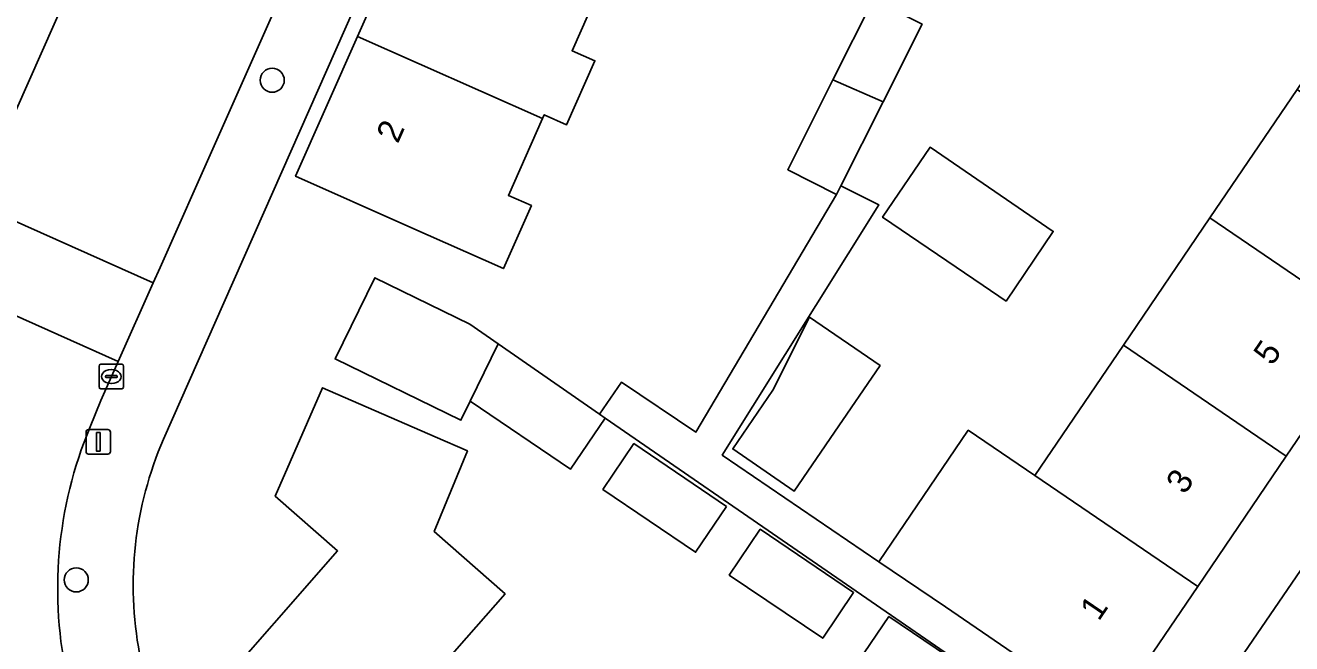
# Model space of a CAD drawing. Extents: x 160023 to 161302, y 384750 to 385707.
# Drawn here: x 160150 to 160201.5, y 385275.6 to 385300.7 of the extents above; entities that cross this region are included whole.
import ezdxf

# ---------------------------------------------------------------- set-up
doc = ezdxf.new("R2010")
doc.units = 0
for name, color, linetype in [('IMGEO_Boom', 7, 'Continuous'), ('IMGEO_Erf', 7, 'Continuous'), ('IMGEO_Kolk', 7, 'Continuous'), ('IMGEO_Lichtmast', 7, 'Continuous'), ('IMGEO_Pand', 7, 'Continuous'), ('IMGEO_Pand_nummerreeks', 7, 'Continuous'), ('IMGEO_Rijbaan_lokaal_gesloten', 7, 'Continuous'), ('IMGEO_Rijbaan_lokaal_open', 7, 'Continuous'), ('IMGEO_Voetpad_open', 7, 'Continuous')]:
    doc.layers.add(name, color=color, linetype=linetype)

msp = doc.modelspace()

# ---------------------------------------------------------------- linework, layer by layer
at = {"layer": 'IMGEO_Boom'}
for centre in [(160160.018, 385298.496), (160152.044, 385278.181)]:
    msp.add_circle(centre, 0.489, dxfattribs=at)
at = {"layer": 'IMGEO_Erf'}
for points in [[(160183.431, 385346.744), (160159.311, 385292.29), (160158.414, 385290.267), (160155.597, 385283.906)], [(160173.529, 385302.648), (160172.22, 385299.697), (160173.147, 385299.286), (160171.995, 385296.689), (160171.085, 385297.093), (160171.015, 385296.934), (160169.631, 385293.814), (160170.564, 385293.401), (160169.426, 385290.836), (160165.536, 385292.563), (160160.965, 385294.59), (160163.487, 385300.274), (160166.018, 385305.98)], [(160186.466, 385300.778), (160184.874, 385297.615), (160183.158, 385294.204), (160184.707, 385293.425), (160178.329, 385283.256), (160184.707, 385278.922), (160188.342, 385284.267), (160191.051, 385282.425), (160194.656, 385287.725), (160198.174, 385292.898), (160201.722, 385298.115), (160205.269, 385303.332)], [(160190.417, 385273.159), (160173.571, 385284.757), (160172.15, 385282.683), (160168.075, 385285.45), (160167.694, 385284.67), (160162.577, 385287.169), (160164.187, 385290.467), (160168.065, 385288.573), (160169.21, 385287.779), (160173.331, 385284.924), (160174.229, 385286.22), (160177.261, 385284.188), (160182.983, 385293.857), (160180.994, 385294.858), (160182.836, 385298.519), (160184.476, 385301.779)], [(160157.419, 385273.368), (160162.676, 385279.36), (160160.143, 385281.583), (160162.064, 385285.991), (160166.648, 385283.994), (160167.959, 385283.423), (160166.609, 385280.144), (160169.496, 385277.611), (160167.531, 385275.372)]]:
    msp.add_lwpolyline(points, dxfattribs=at)
for points in [[(160221.619, 385307.412), (160218.975, 385309.223), (160215.422, 385303.999), (160211.901, 385298.822), (160208.353, 385293.604), (160204.806, 385288.388), (160201.287, 385283.214), (160197.683, 385277.915), (160194.049, 385272.571), (160196.571, 385270.843)], [(160186.787, 385295.774), (160191.803, 385292.348), (160189.88, 385289.515), (160188.943, 385290.151), (160184.854, 385292.928)], [(160180.395, 385285.892), (160181.882, 385288.862), (160184.754, 385286.898), (160182.895, 385284.181), (160181.262, 385281.794), (160178.762, 385283.505)], [(160178.509, 385281.166), (160177.249, 385279.307), (160173.478, 385281.86), (160174.737, 385283.72)], [(160183.679, 385277.665), (160182.419, 385275.806), (160178.617, 385278.38), (160179.877, 385280.239)], [(160188.923, 385274.114), (160187.664, 385272.254), (160183.852, 385274.836), (160185.112, 385276.695)]]:
    msp.add_lwpolyline(points, close=True, dxfattribs=at)
msp.add_arc((160169.229, 385277.966), 14.87, 156.4566, 190.8082, dxfattribs=at)
at = {"layer": 'IMGEO_Kolk'}
for p, q in [((160152.97, 385286.024), (160152.97, 385286.876)), ((160153.045, 385286.95), (160153.897, 385286.95)), ((160153.458, 385286.73), (160153.483, 385286.73)), ((160153.971, 385286.876), (160153.971, 385286.024)), ((160153.229, 385286.444), (160153.229, 385286.456)), ((160153.667, 385286.407), (160153.269, 385286.407)), ((160153.272, 385286.493), (160153.67, 385286.493)), ((160153.481, 385286.17), (160153.456, 385286.17)), ((160153.713, 385286.456), (160153.713, 385286.444)), ((160153.897, 385285.95), (160153.045, 385285.95))]:
    msp.add_line(p, q, dxfattribs=at)
for points in [[(160152.97, 385286.024), (160152.97, 385286.876)], [(160153.045, 385286.95), (160153.897, 385286.95)], [(160153.971, 385286.876), (160153.971, 385286.024)], [(160153.897, 385285.95), (160153.045, 385285.95)]]:
    msp.add_lwpolyline(points, dxfattribs=at)
for centre, radius, start, end in [((160153.047, 385286.874), 0.0765, 91.552, 178.448), ((160153.047, 385286.874), 0.0765, 91.552, 178.448), ((160153.895, 385286.874), 0.0765, 1.552, 88.448), ((160153.895, 385286.874), 0.0765, 1.552, 88.448), ((160153.269, 385286.453), 0.0403, 85.8775, 175.7526), ((160153.266, 385286.443), 0.0366, 178.938, 274.7102), ((160153.67, 385286.45), 0.043, 264.8664, 352.4533), ((160153.674, 385286.455), 0.0386, 1.7309, 96.639), ((160153.047, 385286.026), 0.0765, 181.552, 268.448), ((160153.047, 385286.026), 0.0765, 181.552, 268.448), ((160153.895, 385286.026), 0.0765, 271.552, 358.448), ((160153.895, 385286.026), 0.0765, 271.552, 358.448)]:
    msp.add_arc(centre, radius, start, end, dxfattribs=at)
for centre, major_axis, ratio, start_param, end_param in [((160153.457, 385286.45), (-0.387, 0.002), 0.722429, 4.712389, 7.853982), ((160153.482, 385286.45), (-0.39, 0.002), 0.717154, 1.570796, 4.712389)]:
    msp.add_ellipse(centre, major_axis=major_axis, ratio=ratio, start_param=start_param, end_param=end_param, dxfattribs=at)
at = {"layer": 'IMGEO_Lichtmast'}
for p, q in [((160152.441, 385283.394), (160152.441, 385284.194)), ((160152.441, 385284.194), (160152.441, 385283.394)), ((160152.541, 385284.294), (160153.331, 385284.294)), ((160153.331, 385284.294), (160152.541, 385284.294)), ((160153.431, 385284.194), (160153.431, 385283.394)), ((160153.431, 385283.394), (160153.431, 385284.194)), ((160153.331, 385283.294), (160152.541, 385283.294)), ((160152.541, 385283.294), (160153.331, 385283.294))]:
    msp.add_line(p, q, dxfattribs=at)
msp.add_lwpolyline([(160152.861, 385284.169), (160153.011, 385284.169), (160153.011, 385283.419), (160152.861, 385283.419), (160152.861, 385284.169)], dxfattribs=at)
for centre, start, end in [((160152.541, 385284.194), 90, 180), ((160152.541, 385284.194), 90, 180), ((160153.331, 385284.194), 0, 90), ((160153.331, 385284.194), 360, 90), ((160152.541, 385283.394), 180, 270), ((160152.541, 385283.394), 180, 270), ((160153.331, 385283.394), 270, 0), ((160153.331, 385283.394), 270, 0)]:
    msp.add_arc(centre, 0.1, start, end, dxfattribs=at)
at = {"layer": 'IMGEO_Pand'}
for points in [[(160166.018, 385305.98), (160163.487, 385300.274), (160171.015, 385296.934), (160171.085, 385297.093), (160171.995, 385296.689), (160173.147, 385299.286), (160172.22, 385299.697), (160173.529, 385302.648)], [(160182.836, 385298.519), (160184.874, 385297.615), (160186.466, 385300.778), (160184.476, 385301.779)], [(160163.487, 385300.274), (160160.965, 385294.59), (160165.536, 385292.563), (160169.426, 385290.836), (160170.564, 385293.401), (160169.631, 385293.814), (160171.015, 385296.934)], [(160184.874, 385297.615), (160182.836, 385298.519), (160180.994, 385294.858), (160182.983, 385293.857), (160183.158, 385294.204)], [(160201.722, 385298.115), (160198.174, 385292.898), (160204.806, 385288.388), (160208.353, 385293.604)], [(160188.943, 385290.151), (160189.88, 385289.515), (160191.803, 385292.348), (160186.787, 385295.774), (160184.854, 385292.928)], [(160201.287, 385283.214), (160204.806, 385288.388), (160198.174, 385292.898), (160194.656, 385287.725)], [(160169.21, 385287.779), (160168.065, 385288.573), (160164.187, 385290.467), (160162.577, 385287.169), (160167.694, 385284.67), (160168.075, 385285.45)], [(160180.395, 385285.892), (160178.762, 385283.505), (160181.262, 385281.794), (160182.895, 385284.181), (160184.754, 385286.898), (160181.882, 385288.862)], [(160169.21, 385287.779), (160168.075, 385285.45), (160172.15, 385282.683), (160173.571, 385284.757), (160173.331, 385284.924)], [(160197.683, 385277.915), (160201.287, 385283.214), (160194.656, 385287.725), (160191.051, 385282.425)], [(160166.609, 385280.144), (160167.959, 385283.423), (160166.648, 385283.994), (160162.064, 385285.991), (160160.143, 385281.583), (160162.676, 385279.36), (160157.419, 385273.368), (160162.139, 385269.227), (160167.531, 385275.372), (160169.496, 385277.611)], [(160197.683, 385277.915), (160191.051, 385282.425), (160188.342, 385284.267), (160184.707, 385278.922), (160187.417, 385277.081), (160189.916, 385275.383), (160194.049, 385272.571)], [(160178.509, 385281.166), (160174.737, 385283.72), (160173.478, 385281.86), (160177.249, 385279.307)], [(160178.617, 385278.38), (160182.419, 385275.806), (160183.679, 385277.665), (160179.877, 385280.239)], [(160188.923, 385274.114), (160185.112, 385276.695), (160183.852, 385274.836), (160187.664, 385272.254)]]:
    msp.add_lwpolyline(points, close=True, dxfattribs=at)
at = {"layer": 'IMGEO_Rijbaan_lokaal_gesloten'}
for points in [[(160161.865, 385325.106), (160155.004, 385309.501), (160147.908, 385293.496), (160155.175, 385290.263), (160155.452, 385290.886), (160156.947, 385294.248), (160182.332, 385351.312), (160183.877, 385354.785), (160186.831, 385361.426), (160179.518, 385364.667), (160162.369, 385325.971)], [(160152.606, 385284.405), (160153.045, 385285.475), (160153.752, 385287.065), (160146.489, 385290.296), (160145.349, 385287.724)]]:
    msp.add_lwpolyline(points, dxfattribs=at)
msp.add_arc((160168.331, 385277.827), 17.045, 157.2994, 192.8127, dxfattribs=at)
at = {"layer": 'IMGEO_Rijbaan_lokaal_open'}
msp.add_lwpolyline([(160147.908, 385293.496), (160146.489, 385290.296), (160153.752, 385287.065), (160155.175, 385290.263)], close=True, dxfattribs=at)
at = {"layer": 'IMGEO_Voetpad_open'}
for points in [[(160189.867, 385368.251), (160189.568, 385367.579), (160188.235, 385364.58), (160186.831, 385361.426), (160183.877, 385354.785), (160182.332, 385351.312), (160156.947, 385294.248), (160155.452, 385290.886), (160155.175, 385290.263), (160153.752, 385287.065), (160153.045, 385285.475), (160152.606, 385284.405)], [(160155.597, 385283.906), (160158.414, 385290.267), (160159.311, 385292.29), (160183.431, 385346.744)], [(160241.887, 385328.157), (160244.13, 385331.418), (160236.144, 385332.974), (160232.498, 385327.657), (160231.862, 385328.093), (160230.884, 385326.666), (160231.079, 385326.532), (160233.506, 385324.768), (160222.754, 385309.07), (160221.619, 385307.412), (160196.571, 385270.843), (160195.714, 385269.592), (160194.296, 385267.521), (160186.568, 385258.673), (160181.176, 385252.527), (160180.818, 385252.107)], [(160145.349, 385287.724), (160146.489, 385290.296), (160147.908, 385293.496), (160155.004, 385309.501)]]:
    msp.add_lwpolyline(points, dxfattribs=at)
msp.add_lwpolyline([(160189.916, 385275.383), (160187.417, 385277.081), (160184.707, 385278.922), (160178.329, 385283.256), (160184.707, 385293.425), (160183.158, 385294.204), (160182.983, 385293.857), (160177.261, 385284.188), (160174.229, 385286.22), (160173.331, 385284.924), (160173.571, 385284.757), (160190.417, 385273.159), (160194.363, 385270.502), (160195.714, 385269.592), (160196.571, 385270.843), (160194.049, 385272.571)], close=True, dxfattribs=at)
for centre, radius, start, end in [((160168.331, 385277.827), 17.045, 157.2994, 192.8127), ((160169.229, 385277.966), 14.87, 156.4566, 190.8082)]:
    msp.add_arc(centre, radius, start, end, dxfattribs=at)

# ---------------------------------------------------------------- texts
at = {"layer": 'IMGEO_Pand_nummerreeks'}
for s, rotation, p in [('2', 66.0775, (160165.13, 385295.89)), ('5', 55.7815, (160200.712, 385286.851)), ('3', 55.7815, (160197.151, 385281.615)), ('1', 55.7832, (160193.654, 385276.472))]:
    msp.add_text(s, height=1, rotation=rotation, dxfattribs=at).set_placement(p)

doc.saveas('drawing.dxf')
